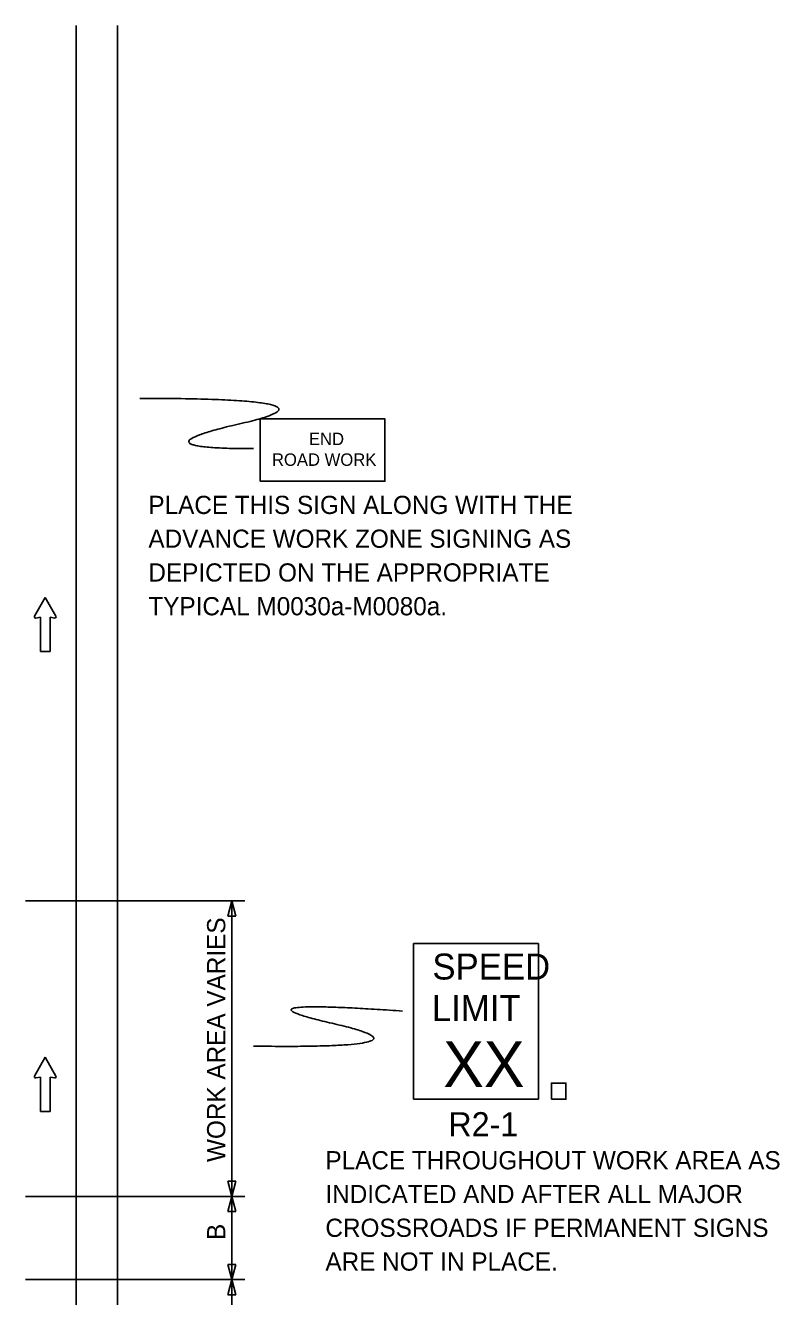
# Model space of a CAD drawing. Extents: x 16743 to 18475, y 7218 to 8262.
# Drawn here: x 17093.6 to 17383.9, y 7726.9 to 8216.2 of the extents above; entities that cross this region are included whole.
import ezdxf

# ---------------------------------------------------------------- set-up
doc = ezdxf.new("R2010")
doc.units = 0
for name, color, linetype in [('MT_SCRATCH_LEVEL_E', 7, 'Continuous'), ('PAVT_EDGE_EX', 7, 'Continuous'), ('TRAFFIC_SIGNS_PR', 7, 'Continuous'), ('TYPICAL_TEXT_DIMEN_PR', 7, 'Continuous')]:
    doc.layers.add(name, color=color, linetype=linetype)

msp = doc.modelspace()

# ---------------------------------------------------------------- linework, layer by layer
at = {"layer": 'MT_SCRATCH_LEVEL_E'}
for p, q in [((17101.19, 7996.03), (17097.08, 7988.79)), ((17101.19, 7996.03), (17097.08, 7988.79)), ((17105.33, 7988.79), (17101.19, 7996.03)), ((17105.33, 7988.79), (17101.19, 7996.03)), ((17097.56, 7988.11), (17099.33, 7988.43)), ((17097.56, 7988.11), (17099.33, 7988.43)), ((17099.33, 7988.43), (17099.33, 7975.17)), ((17099.33, 7988.43), (17099.33, 7975.17)), ((17103.08, 7975.17), (17103.08, 7988.43)), ((17103.08, 7988.43), (17104.85, 7988.11)), ((17103.08, 7975.17), (17103.08, 7988.43)), ((17103.08, 7988.43), (17104.85, 7988.11)), ((17099.33, 7975.17), (17103.08, 7975.17)), ((17099.33, 7975.17), (17103.08, 7975.17)), ((17101.19, 7819.01), (17097.08, 7811.77)), ((17101.19, 7819.01), (17097.08, 7811.77)), ((17105.33, 7811.77), (17101.19, 7819.01)), ((17105.33, 7811.77), (17101.19, 7819.01)), ((17097.56, 7811.09), (17099.33, 7811.4)), ((17097.56, 7811.09), (17099.33, 7811.4)), ((17099.33, 7811.4), (17099.33, 7798.14)), ((17099.33, 7811.4), (17099.33, 7798.14)), ((17103.08, 7798.14), (17103.08, 7811.4)), ((17103.08, 7811.4), (17104.85, 7811.09)), ((17103.08, 7798.14), (17103.08, 7811.4)), ((17103.08, 7811.4), (17104.85, 7811.09)), ((17099.33, 7798.14), (17103.08, 7798.14)), ((17099.33, 7798.14), (17103.08, 7798.14))]:
    msp.add_line(p, q, dxfattribs=at)
for centre, start, end in [((17097.48, 7988.57), 150.4248, 279.9638), ((17097.48, 7988.57), 150.4248, 279.9638), ((17104.92, 7988.57), 260.0362, 29.7731), ((17104.92, 7988.57), 260.0362, 29.7731), ((17097.48, 7811.54), 150.4248, 279.9638), ((17097.48, 7811.54), 150.4248, 279.9638), ((17104.92, 7811.54), 260.0362, 29.7731), ((17104.92, 7811.54), 260.0362, 29.7731)]:
    msp.add_arc(centre, 0.463, start, end, dxfattribs=at)
at = {"layer": 'PAVT_EDGE_EX'}
for p, q in [((17113.08, 8216.25), (17113.08, 7378.68)), ((17129.08, 8216.25), (17129.08, 7378.68))]:
    msp.add_line(p, q, dxfattribs=at)
at = {"layer": 'TRAFFIC_SIGNS_PR'}
for p, q in [((17243.05, 7862.88), (17291.05, 7862.88)), ((17243.05, 7802.88), (17243.05, 7862.88)), ((17291.05, 7802.88), (17291.05, 7862.88)), ((17243.05, 7802.88), (17291.05, 7802.88))]:
    msp.add_line(p, q, dxfattribs=at)
for points in [[(17183.98, 8040.77), (17231.98, 8040.77), (17231.98, 8064.77), (17183.98, 8064.77)], [(17296.06, 7802.88), (17301.66, 7802.88), (17301.66, 7809.05), (17296.06, 7809.05)]]:
    msp.add_lwpolyline(points, close=True, dxfattribs=at)
for points in [[(17181.33, 8053.32), (17134.1, 8053.32), (17219.12, 8072.67), (17137.64, 8072.67)], [(17238.76, 7836.8), (17169.54, 7841.69), (17254.56, 7822.34), (17181.4, 7823.3)]]:
    msp.add_open_spline(points, degree=2, dxfattribs=at)
at = {"layer": 'TYPICAL_TEXT_DIMEN_PR'}
for p, q in [((17178.08, 7879.2), (17093.58, 7879.2)), ((17171.51, 7873.34), (17173.08, 7879.2)), ((17173.08, 7765.48), (17173.08, 7879.2)), ((17173.08, 7879.2), (17174.65, 7873.34)), ((17173.08, 7873.34), (17171.51, 7873.34)), ((17174.65, 7873.34), (17173.08, 7873.34)), ((17173.08, 7765.48), (17171.51, 7771.34)), ((17171.51, 7771.34), (17173.08, 7771.34)), ((17173.08, 7771.34), (17174.65, 7771.34)), ((17174.65, 7771.34), (17173.08, 7765.48)), ((17178.08, 7765.48), (17093.58, 7765.48)), ((17171.51, 7759.61), (17173.08, 7765.48)), ((17173.08, 7733.42), (17173.08, 7765.48)), ((17173.08, 7765.48), (17174.65, 7759.61)), ((17173.08, 7759.61), (17171.51, 7759.61)), ((17174.65, 7759.61), (17173.08, 7759.61)), ((17173.08, 7733.42), (17171.51, 7739.28)), ((17171.51, 7739.28), (17173.08, 7739.28)), ((17173.08, 7739.28), (17174.65, 7739.28)), ((17174.65, 7739.28), (17173.08, 7733.42)), ((17178.08, 7733.42), (17093.58, 7733.42)), ((17171.51, 7727.56), (17173.08, 7733.42)), ((17173.08, 7733.42), (17174.65, 7727.56)), ((17173.08, 7702.84), (17173.08, 7733.42)), ((17173.08, 7727.56), (17171.51, 7727.56)), ((17174.65, 7727.56), (17173.08, 7727.56))]:
    msp.add_line(p, q, dxfattribs=at)

# ---------------------------------------------------------------- texts
at = {"layer": 'TRAFFIC_SIGNS_PR'}
for s, height, p in [('END', 4.789, (17202.73, 8054.68)), ('ROAD WORK', 4.789, (17188.49, 8046.7)), ('PLACE THIS SIGN ALONG WITH THE', 7, (17140.92, 8028.16)), ('ADVANCE WORK ZONE SIGNING AS', 7, (17140.92, 8015.16)), ('DEPICTED ON THE APPROPRIATE', 7, (17140.92, 8002.16)), ('TYPICAL M0030a-M0080a.', 7, (17140.92, 7989.16)), ('SPEED', 10, (17250.26, 7848.95)), ('LIMIT', 10, (17250.05, 7832.95)), ('XX', 17.538, (17254.44, 7807.57)), ('R2-1', 9.3, (17256.39, 7788.58)), ('PLACE THROUGHOUT WORK AREA AS', 7, (17209.08, 7775.88)), ('INDICATED AND AFTER ALL MAJOR', 7, (17209.08, 7762.88)), ('CROSSROADS IF PERMANENT SIGNS', 7, (17209.08, 7749.88)), ('ARE NOT IN PLACE.', 7, (17209.08, 7736.88))]:
    msp.add_text(s, height=height, dxfattribs=at).set_placement(p)
at = {"layer": 'TYPICAL_TEXT_DIMEN_PR'}
for s, p in [('WORK AREA VARIES', (17170.52, 7778.7)), ('B', (17170.52, 7748.68))]:
    msp.add_text(s, height=7, rotation=90, dxfattribs=at).set_placement(p)

doc.saveas('drawing.dxf')
